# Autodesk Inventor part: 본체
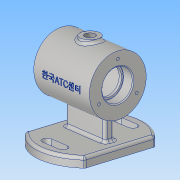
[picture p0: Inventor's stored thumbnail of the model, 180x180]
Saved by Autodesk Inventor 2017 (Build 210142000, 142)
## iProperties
Part Number: 본체
Material: 알루미늄 6061
Document SubType Name: Modeling
Designer: user
Density: 2.7 g/cm^3
Appearance: 알루미늄 - 평지
Mass: 467.937 g
Surface Area: 487.008 cm^2
Volume: 173.31 cm^3
Author: user
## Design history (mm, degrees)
sketch "스케치3"
  geometry: L1 (37.5, 52.5)-(-37.5, 52.5); L2 (-37.5, -52.5)-(37.5, -52.5); L3 (37.5, 52.5)-(-37.5, -52.5); L4 (-37.5, 52.5)-(37.5, -52.5); C1 r 52.5 at (0, 0); 1 further point
  constraints: 8 end point, 1 centre point, 1 coincident, 1 horizontal, 1 parallel
  dimensions: "d13" = 75 distance of L2.start L2.end; "d14" = 105 distance of L1.end L2.start; "d19" = 52.5 vertical distance of point (0, 0) L2.end; "d20" = 52.5 distance from line of L1 point (0, 0); "d92" = 105 diameter of C1
extrude "돌출1" new body sketch "스케치3" distance "d7" = 10; taper "d8" = 0 deg
sketch "스케치6"
  geometry: L1 (35, 92)-(-35, 92); L2 (-35, 92)-(-35, 62); L3 (-35, 62)-(35, 62); L4 (35, 62)-(35, 92); L5 (-52.5, 0)-(52.5, 0) reference; 2 further points
  constraints: 8 end point, 2 parallel, 1 horizontal, 1 midpoint, 1 perpendicular, 1 vertical alignment
  dimensions: "d21" = 70 distance of L1.start L1.end; "d23" = 60 diameter of L1 L3; "d95" = 62 distance between parallel lines of L5 L3
revolve "회전1" sketch "스케치6" stored, may be unused: angle "d24" = 90 deg
sketch "스케치8"
  geometry: L1 (-35, 32)-(-35, 92) reference; L2 (35, 32)-(35, 92) reference; L3 (35, 62)-(-35, 62); L4 (-35, 62)-(-35, 78); L5 (-35, 78)-(-23, 78); L6 (-23, 78)-(-23, 76); L7 (-23, 76)-(-20, 76); L8 (-20, 76)-(-20, 87); L9 (-20, 87)-(20, 87); L10 (20, 87)-(20, 76); L11 (20, 76)-(23, 76); L12 (23, 76)-(23, 78); L13 (23, 78)-(35, 78); L14 (35, 78)-(35, 62); 1 further point
  constraints: 24 end point, 6 perpendicular, 3 point on line, 2 horizontal, 2 midpoint, 1 collinear, 1 parallel
  dimensions: "d30" = 32 diameter of L5 L3; "d31" = 28 diameter of L7 L3; "d32" = 32 diameter of L13 L3; "d33" = 12 distance of L4.end L5.end; "d34" = 3 distance of L6.end L7.end; "d35" = 40 distance of L8.end L9.end; "d36" = 12 distance of L12.end L13.end; "d37" = 50 diameter of L9 L3
revolve "회전2" sketch "스케치8" stored, may be unused: angle "d38" = 90 deg
node "작업 평면1"
sketch "스케치9"
  geometry: C1 r 10 at (0, 0); 1 further point
  constraints: 1 centre point, 1 coincident
  dimensions: "d40" = 20 diameter of C1
extrude "돌출3" join sketch "스케치9" stored distance "d41" = 10; taper "d42" = 0 deg
sketch "스케치10"
  geometry: C1 r 10 at (0, 0) reference; 1 further point
  constraints: 1 coincident
hole "구멍1" sketch "스케치10" at (0, 0) diameter "d43" = 10.917; stored, may be unused: countersink angle "d47" = 90 deg, drill point angle "d49" = 118 deg; dims "d44" = 24, "d45" = 4, "d46" = 2, "d48" = 29.1
sketch "스케치11"
  geometry: L1 (0, 0)-(21.878, 0); L2 (0, 0)-(0, 23); L3 (0, 0)-(-19.919, -11.5); L4 (0, 0)-(23, 0); C1 r 30 at (0, 0) reference; A1 r 23 centre (0, 0) between (0, 23) and (-19.919, -11.5); 4 further points
  constraints: 8 end point, 2 coincident, 2 horizontal, 2 point on circle, 1 centre point, 1 equal length, 1 vertical, 4 other
  dimensions: "d50" = 46 diameter of A1; "d53" = 120 deg angle of L2 L3; "d56" = 360 deg dimension on L1.start point (-19.919, -11.5) (derived)
hole "구멍2" sketch "스케치11" at (-19.919, -11.5), (19.919, -11.5), (0, 23) diameter "d58" = 3.242; stored, may be unused: countersink angle "d62" = 90 deg, drill point angle "d64" = 118 deg; dims "d59" = 8, "d60" = 4, "d61" = 2, "d63" = 10
node "작업 평면3"
fillet "모깎기1" dims "d84" = 0.3
fillet "모깎기2" dims "d85" = 3
chamfer "모따기1" distance "d88" = 1; stored, may be unused: second distance "d89" = 2, angle "d90" = 45 deg
sketch "스케치16"
  geometry: L1 (-57.5, 50)-(-37.5, 50); L2 (-37.5, 50)-(-37.5, -50); L3 (-37.5, -50)-(-57.5, -50); L4 (-57.5, -50)-(-57.5, 50); L5 (37.5, -50)-(57.5, -50); L6 (57.5, -50)-(57.5, 50); L7 (57.5, 50)-(37.5, 50); L8 (37.5, 50)-(37.5, -50); C1 r 52.5 at (0, 0) reference
  constraints: 16 end point, 4 parallel, 2 horizontal, 2 perpendicular
  dimensions: "d110" = 100 distance of L5.end L6.end; "d111" = 20 distance of L6.end L7.end; "d112" = 20 distance of L1.start L1.end; "d113" = 100 distance of L3.end L1.start; "d114" = 50 distance from line of C1.centre L1; "d115" = 50 distance from line of C1.centre L5; "d116" = 37.5 distance from line of L8 C1.centre; "d117" = 75 distance between parallel lines of L2 L8
extrude "돌출7" cut sketch "스케치16" stored distance "d118" = 10; taper "d119" = 0 deg
sketch "스케치17"
  geometry: L1 (-25, 5)-(25, 5); L2 (25, 5)-(25, -5); L3 (25, -5)-(-25, -5); L4 (-25, -5)-(-25, 5); L5 (-25, 5)-(25, -5); L6 (25, 5)-(-25, -5); A1 r 52.5 centre (0, 0) between (-37.5, -36.742) and (37.5, -36.742) reference
  constraints: 12 end point, 2 midpoint, 2 parallel, 1 horizontal, 1 perpendicular
  dimensions: "d120" = 50 distance of L1.start L1.end; "d121" = 10 distance of L1.end L2.end
extrude "돌출8" join sketch "스케치17" stored distance "d122" = 10; taper "d123" = 0 deg
sketch "스케치18"
  geometry: L1 (-10, -37)-(10, -37); L2 (-10, -42)-(10, -42); L3 (10, -32)-(-10, -32); L4 (-10, 37)-(10, 37); L5 (-10, 32)-(10, 32); L6 (10, 42)-(-10, 42); A1 r 52.5 centre (0, 0) between (37.5, 36.742) and (-37.5, 36.742) reference; A2 r 5 centre (-10, -37) between (-10, -32) and (-10, -42); A3 r 5 centre (10, -37) between (10, -42) and (10, -32); A4 r 5 centre (-10, 37) between (-10, 42) and (-10, 32); A5 r 5 centre (10, 37) between (10, 32) and (10, 42); 2 further points
  constraints: 16 end point, 8 point on circle, 8 tangent, 4 centre point, 2 horizontal, 2 midpoint, 2 parallel, 2 vertical alignment
  dimensions: "d124" = 20 distance of L1.start L1.end; "d125" = 10 diameter of A3; "d126" = 37 distance of A1.centre point (0, -37); "d127" = 20 distance of L4.start L4.end; "d128" = 10 diameter of A5; "d129" = 37 distance of point (0, 37) A1.centre
extrude "돌출9" cut sketch "스케치18" distance "d130" = 10; taper "d131" = 0 deg
sketch "스케치19"
  geometry: L1 (-10, 22)-(-10, 82) reference; 2 further points
  constraints: 1 other
  dimensions: "d132" = 35 distance from line of point (25, 52) L1; "d133" = 30 vertical distance of point (25, 52) L1.end
feature "엠보싱2" sketch "스케치19" dims "d134" = 0.5, "d135" = 0
fillet "모깎기5" dims "d136" = 3
fillet "모깎기6" dims "d137" = 3
node "솔리드1"
mirror "미러1"
other parameters: "d0" = 105, "d6" = 105, "d39" = 85
